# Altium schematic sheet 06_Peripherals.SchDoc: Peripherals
size A4; Date: 9/24/2014; Author: P.A.; CompanyName: STMicroelectronics; Organization: Microcontrollers Division; Address1: 12, Rue Jules HOROWITZ; Address2: 38019 Grenoble; Address3: FRANCE; DocumentNumber: 9; Revision: E-01; SheetNumber: 9; SheetTotal: 12; Project: STM32F413H-DISCO
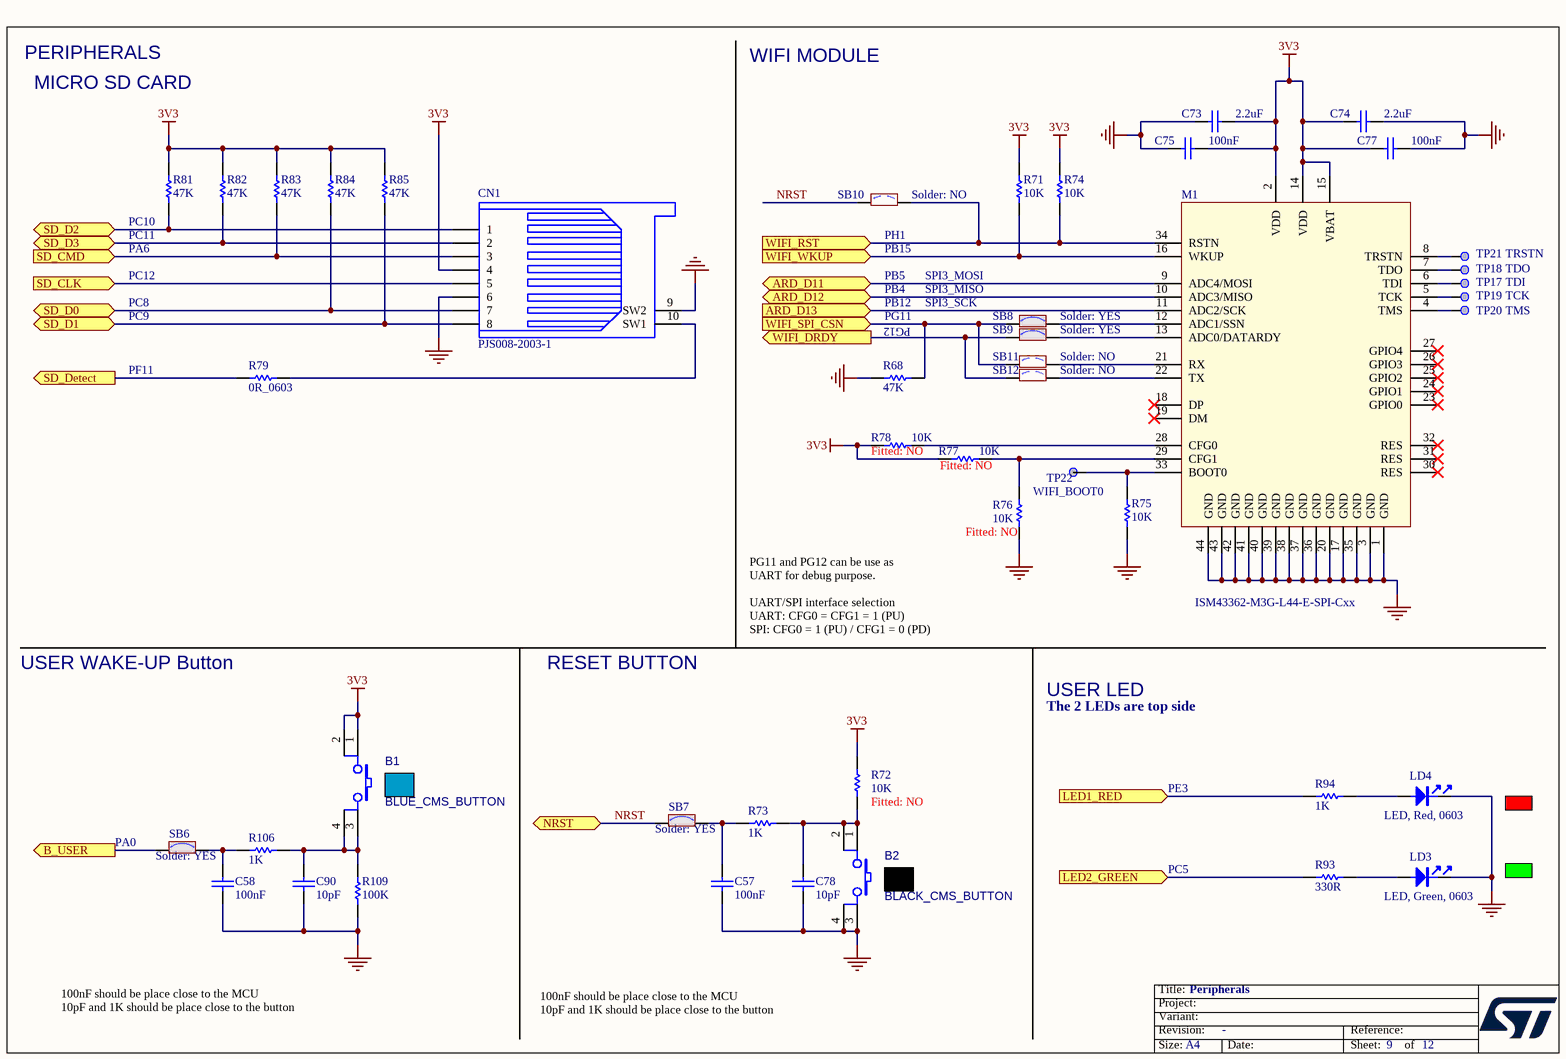
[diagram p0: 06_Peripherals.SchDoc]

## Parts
B1  BLUE_CMS_BUTTON  [SWI_C&K_KSC721GLFS_BLUE]
B2  BLACK_CMS_BUTTON  [SWI_C&K_KSC321GLFS_BLACK]
C57  100nF  [C0402]
C58  100nF  [C0402]
C73  2.2uF  [C0603]
C74  2.2uF  [C0603]
C75  100nF  [C0402]
C77  100nF  [C0402]
C78  10pF  [C0402]
C90  10pF  [C0402]
CN1  PJS008-2003-1  [CON_MICROSD_YAMAICHI_PJS008-2003-1]
LD3  LED, Green, 0603  [LED_0603_GREEN]
LD4  LED, Red, 0603  [LED_0603_RED]
M1  ISM43362-M3G-L44-E-SPI-Cxx  [MOD_WIFI_INVENTEK-SYSTEMS_ISM43362-M3G-L44-E-SPI-CXX]
R68  47K  [R0402]
R71  10K  [R0402]
R72  10K  Fitted: NO  [R0402]
R73  1K  [R0402]
R74  10K  [R0402]
R75  10K  [R0402]
R76  10K  Fitted: NO  [R0402]
R77  10K  Fitted: NO  [R0402]
R78  10K  Fitted: NO  [R0402]
R79  0R_0603  [R0603]
R81  47K  [R0402]
R82  47K  [R0402]
R83  47K  [R0402]
R84  47K  [R0402]
R85  47K  [R0402]
R93  330R  [R0402]
R94  1K  [R0402]
R106  1K  [R0402]
R109  100K  [R0402]
SB6  Solder: YES  [SOLDER-BRIDGE_R0603-0R]  (hidden comment: SB_ON)
SB7  Solder: YES  [SOLDER-BRIDGE_R0603-0R]  (hidden comment: SB_ON)
SB8  Solder: YES  [SOLDER-BRIDGE_R0603-0R]  (hidden comment: SB_ON)
SB9  Solder: YES  [SOLDER-BRIDGE_R0603-0R]  (hidden comment: SB_ON)
SB10  Solder: NO  [SOLDER-BRIDGE_R0603-0R]  (hidden comment: SB_OFF)
SB11  Solder: NO  [SOLDER-BRIDGE_R0603-0R]  (hidden comment: SB_OFF)
SB12  Solder: NO  [SOLDER-BRIDGE_R0603-0R]  (hidden comment: SB_OFF)
TP17  TDI  [TP_SMD_2MM]
TP18  TDO  [TP_SMD_2MM]
TP19  TCK  [TP_SMD_2MM]
TP20  TMS  [TP_SMD_2MM]
TP21  TRSTN  [TP_SMD_2MM]
TP22  WIFI_BOOT0  [TP_SMD_1MM]

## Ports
ARD_D11 (bidir), ARD_D12 (bidir), ARD_D13 (in), B_USER (out), LED1_RED (in), LED2_GREEN (in), NRST (bidir), SD_CLK (in), SD_CMD (in), SD_D0 (bidir), SD_D1 (bidir), SD_D2 (bidir), SD_D3 (bidir), SD_Detect (out), WIFI_DRDY (out), WIFI_RST (in), WIFI_SPI_CSN (in), WIFI_WKUP (in)

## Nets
3V3: B1.1 B1.2 C73.1 C74.1 C75.2 C77.1 CN1.4 M1.2(VDD) M1.14(VDD) M1.15(VBAT) R71.2 R72.2 R74.2 R77.1 R78.1 R81.2 R82.2 R83.2 R84.2 R85.2
GND: B2.3 B2.4 C57.1 C58.1 C73.2 C74.2 C75.1 C77.2 C78.1 C90.1 CN1.6 CN1.9(SW2) LD3.2 LD4.2 M1.1(GND) M1.3(GND) M1.17(GND) M1.20(GND) M1.35(GND) M1.36(GND) M1.37(GND) M1.38(GND) M1.39(GND) M1.40(GND) M1.41(GND) M1.42(GND) M1.43(GND) M1.44(GND) R68.1 R75.2 R76.2 R109.1
ARD_D11: M1.9(ADC4/MOSI) ; port ARD_D11
ARD_D12: M1.10(ADC3/MISO) ; port ARD_D12
ARD_D13: M1.11(ADC2/SCK) ; port ARD_D13
B_USER: SB6.1 ; port B_USER
LED1_RED: R94.2 ; port LED1_RED
LED2_GREEN: R93.1 ; port LED2_GREEN
NRST: SB7.1 SB10.1 ; port NRST
SD_CLK: CN1.5 ; port SD_CLK
SD_CMD: CN1.3 R83.1 ; port SD_CMD
SD_D0: CN1.7 R84.1 ; port SD_D0
SD_D1: CN1.8 R85.1 ; port SD_D1
SD_D2: CN1.1 R81.1 ; port SD_D2
SD_D3: CN1.2 R82.1 ; port SD_D3
SD_Detect: R79.1 ; port SD_Detect
WIFI_DRDY: SB9.1 SB12.1 ; port WIFI_DRDY
WIFI_RST: M1.34(RSTN) R74.1 SB10.2 ; port WIFI_RST
WIFI_SPI_CSN: R68.2 SB8.1 SB11.1 ; port WIFI_SPI_CSN
WIFI_WKUP: M1.16(WKUP) R71.1 ; port WIFI_WKUP
NetB1_3: B1.3 B1.4 C90.2 R106.2 R109.2
NetB2_1: B2.1 B2.2 C78.2 R72.1 R73.2
NetC57_2: C57.2 R73.1 SB7.2
NetC58_2: C58.2 R106.1 SB6.2
NetCN1_10: CN1.10(SW1) R79.2
NetLD3_1: LD3.1 R93.2
NetLD4_1: LD4.1 R94.1
NetM1_4: M1.4(TMS) TP20.1
NetM1_5: M1.5(TCK) TP19.1
NetM1_6: M1.6(TDI) TP17.1
NetM1_7: M1.7(TDO) TP18.1
NetM1_8: M1.8(TRSTN) TP21.1
NetM1_12: M1.12(ADC1/SSN) SB8.2
NetM1_13: M1.13(ADC0/DATARDY) SB9.2
NetM1_21: M1.21(RX) SB11.2
NetM1_22: M1.22(TX) SB12.2
NetM1_28: M1.28(CFG0) R78.2
NetM1_29: M1.29(CFG1) R76.1 R77.2
NetM1_33: M1.33(BOOT0) R75.1 TP22.1

Not connected (* = marked no-connect by the designer): M1 18(DP)* 19(DM)* 23(GPIO0)* 24(GPIO1)* 25(GPIO2)* 26(GPIO3)* 27(GPIO4)* 30(RES)* 31(RES)* 32(RES)*

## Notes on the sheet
- PERIPHERALS
- WIFI MODULE
- MICRO SD CARD
- (near R81) PC10
- (near R81) PC11
- (near R81) PA6
- (near SB10) PB15
- (near SB10) PH1
- PC12
- PC8
- PC9
- PG11
- PB5
- PB4
- PB12
- (near R68) PG12
- SPI3_MOSI
- SPI3_SCK
- SPI3_MISO
- PF11
- PG11 and PG12 can be use as UART for debug purpose.
- USER WAKE-UP Button
- RESET BUTTON
- UART/SPI interface selection
  UART: CFG0 = CFG1 = 1 (PU)
  SPI: CFG0 = 1 (PU) / CFG1 = 0 (PD)
- The 2 LEDs are top side
- USER LED
- PE3
- (near SB6) PA0
- PC5
- 100nF should be place close to the MCU
  10pF and 1K should be place close to the button

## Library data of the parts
B1 = Tactile_switch_CMS_BLUE_2.25N: Manuf_1: C&K; Manuf_Part_1: KSC721GLFS; Ref St: .; Ordered_By: Subcon; Fitted: YES
B2 = Tactile_switch_CMS_BLACK_2N: Manuf_1: C&K; Manuf_Part_1: KSC321GLFS; Ref St: .; Ordered_By: Subcon; Fitted: YES
C57 C58 C75 C77 = Cap_100nF_X7R_10%_0402: Capacitor,100nF,16V,X7R,10%,0402,YAGEO; Manuf_Part_1: CC0402KRX7R7BB104; Fitted: YES; Ordered_By: Subcon
C73 C74 = Cap_2.2uF_X5R_10%_0603: Capacitor,2.2uF,10V, X5R,10%,0603,YAGEO; Manuf_Part_1: CC0603KRX5R6BB225; Manuf_Part_2: C0603C225K8PACTU; Manuf_2: KEMET; Fitted: YES; Ordered_By: Subcon
C78 C90 = Cap_10pF_NPO_5%_0402: Capacitor,10pF,50V,NPO,5%,0402,YAGEO; Manuf_Part_1: CC0402JRNPO9BN100; Fitted: YES; Ordered_By: subcon
CN1 = microSD-PJS008-2003: Memory Card Connectors MicroSD Card Conn Revrs Mnt Push-Push; Manuf_1: YAMAICHI; Fitted: YES; Ordered_By: Subcon
LD3 = LED_green: Manuf_1: everlight; Manuf_Part_1: 19-213SYGC/S530-E2/TR8; ECCN_US/EU: EAR99/NEC; Fitted: YES; Ordered_By: Subcon
LD4 = LED_red: Manuf_1: everlight; Manuf_Part_1: 19-213-R6C-AP1Q2B/3T; ECCN_US/EU: EAR99/NEC; Fitted: YES; Ordered_By: Subcon
M1 = ISM43362-M3G-L44-E: WIFI Module ISM43362-M3G-L44-E: IEEE802.11 b/g/n integrated Antenna; Manuf_1: Inventek; ECCN_US/EU: EAR99; Ordered_By: Subcon; Fitted: YES
R68 = Res_47K_1%_0402: Resistor,47K,0402,1%,YAGEO; Manuf_Part_1: RC0402FR-0747KL; Order_Code: 9239430; Fitted: YES; Ordered_By: Subcon
R71 R74 R75 = Res_10K_1%_0402: Resistor,10K,0402,1%,YAGEO; Manuf_Part_1: RC0402FR-0710KL; Fitted: YES; Ordered_By: subcon
R72 R76-R78 = Res_10K_1%_0402: Resistor,10K,0402,1%,YAGEO; Manuf_Part_1: RC0402FR-0710KL; Ordered_By: subcon
R73 R94 R106 = Res_1K_1%_0402: Resistor,1K,0402,1%,YAGEO; Manuf_Part_1: RC0402FR-071KL; Fitted: YES; Ordered_By: Subcon
R79 = Res_0_5%_0603: Resistor,0R,0603,5%,YAGEO; Manuf_Part_1: RC0603JR-070RL; Fitted: YES; Order_Code: 2363481; Ordered_By: subcon
R81-R85 = Res_47K_1%_0402: Resistor,47K,0402,1%,YAGEO; Manuf_Part_1: RC0402FR-0747KL; Fitted: YES; Order_Code: 9239430; Ordered_By: Subcon
R93 = Res_330_1%_0402: Resistor,330R,0402,1%,YAGEO; Manuf_Part_1: RC0402FR-07330RL; Fitted: YES; Ordered_By: Subcon
R109 = Res_100K_1%_0402: Resistor,100K,0402,1%,YAGEO; Manuf_Part_2: RT0402FRE07100KL; Manuf_Part_1: RC0402FR-07100KL; Fitted: YES; Ordered_By: Subcon
SB6-SB9 = SB_ON: Solder Bridge ON; Ordered_by: Subcon
SB10-SB12 = SB_OFF: Solder Bridge OFF; Fitted: NO; Ordered_By: Subcon
TP17-TP21 = TP 2mm: Test Point; Fitted: YES; Ordered_By: Subcon
TP22 = TP 1mm: Test Point; Fitted: YES; Ordered_By: Subcon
